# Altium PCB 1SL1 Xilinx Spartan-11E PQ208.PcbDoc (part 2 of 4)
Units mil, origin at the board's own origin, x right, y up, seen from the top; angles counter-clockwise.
Board outline 7086.61 x 1988.19 mil, 2 copper layers (Top Layer, Bottom Layer), stack 29.698 mil thick; 115 components, 126 nets, 642 pads, 225 vias.
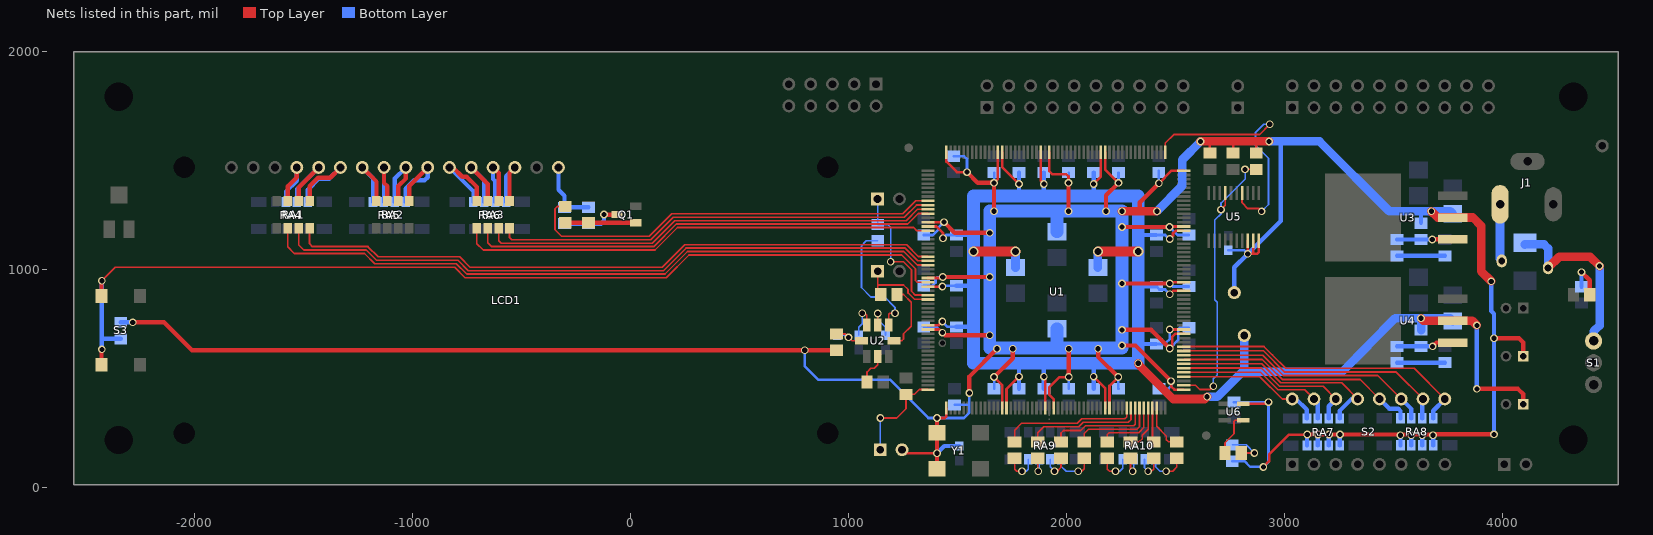
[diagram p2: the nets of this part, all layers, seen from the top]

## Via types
v1: diameter 35.43, hole 23.62, Top Layer to Bottom Layer, tented both sides, 168 vias
v2: diameter 59.06, hole 31.5, Top Layer to Bottom Layer, tented both sides, 27 vias
v3: diameter 47.24, hole 31.5, Top Layer to Bottom Layer, 18 vias
v4: diameter 47.24, hole 31.5, Top Layer to Bottom Layer, tented both sides, 11 vias
v5: diameter 35.43, hole 23.62, Top Layer to Bottom Layer, 1 vias

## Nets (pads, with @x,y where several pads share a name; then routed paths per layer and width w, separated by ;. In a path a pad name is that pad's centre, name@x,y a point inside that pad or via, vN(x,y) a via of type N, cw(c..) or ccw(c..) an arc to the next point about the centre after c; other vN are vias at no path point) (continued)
LCD_DB4: RA3.5 U1.15 | length 2201.6
  Top Layer w7.87: RA3.5@-704.87,1188.03 -704.87,1116.37 -676.13,1087.63 112.14,1087.63 215.49,1190.98 1298.78,1190.98 1313.55,1176.21 U1.15@1364.23,1176.21
LCD_DB5: RA3.6 U1.11 | length 2155.9
  Top Layer w7.87: RA3.6@-654.87,1188.03 -654.87,1121.49 -636.76,1103.38 105.62,1103.38 208.97,1206.72 1271.59,1206.72 1319.82,1254.95 U1.11@1364.23,1254.95
LCD_DB6: RA3.7 U1.10 | length 2095.7
  Top Layer w7.87: RA3.7@-604.87,1188.03 -604.87,1130.54 -593.45,1119.13 99.1,1119.13 202.44,1222.47 1263.83,1222.47 1316,1274.64 U1.10@1364.23,1274.64
LCD_DB7: RA3.8 U1.9 | length 2032.6
  Top Layer w7.87: RA3.8@-554.87,1188.03 -554.87,1144.52 -545.22,1134.87 92.57,1134.87 195.92,1238.22 1255.96,1238.22 1312.06,1294.32 U1.9@1364.23,1294.32
LCD_DB#0: LCD1.7 RA2.4 RA5.5 | length 360.5
  Top Layer w19.68: LCD1.7@-1230.65,1466.57 -1165.5,1401.41 RA2.4@-1165.5,1312.03
  Bottom Layer w19.68: LCD1.7@-1230.65,1466.57 -1181.24,1417.16 RA5.5@-1181.24,1308.09
LCD_DB#1: LCD1.8 RA2.3 RA5.6 | length 319.5
  Top Layer w19.68: LCD1.8@-1130.65,1466.57 -1130.65,1395.7 -1115.5,1380.54 RA2.3@-1115.5,1312.03
  Bottom Layer w19.68: RA5.6@-1131.24,1308.09 -1131.24,1465.98 LCD1.8@-1130.65,1466.57
LCD_DB#2: LCD1.9 RA2.2 RA5.7 | length 348.4
  Top Layer w19.68: RA2.2@-1065.5,1312.03 -1065.5,1380.94 -1030.65,1415.78 LCD1.9@-1030.65,1466.57
  Bottom Layer w19.68: RA5.7@-1081.24,1308.09 -1081.24,1415.98 LCD1.9@-1030.65,1466.57
LCD_DB#3: LCD1.10 RA2.1 RA5.8 | length 417.5
  Top Layer w19.68: RA2.1@-1015.5,1312.03 -1015.5,1381.72 LCD1.10@-930.65,1466.57
  Bottom Layer w19.68: RA5.8@-1031.24,1308.09 -1031.24,1368.34 -992.07,1407.51 -944.83,1407.51 -930.65,1421.68 LCD1.10@-930.65,1466.57
LCD_DB#4: LCD1.11 RA3.4 RA6.5 | length 431.4
  Top Layer w19.68: LCD1.11@-830.65,1466.57 -814.91,1466.57 -771.73,1423.39 -752.05,1423.39 -704.87,1376.21 RA3.4@-704.87,1312.03
  Bottom Layer w19.68: LCD1.11@-830.65,1466.57 -720.61,1356.53 RA6.5@-720.61,1308.09
LCD_DB#5: LCD1.12 RA3.3 RA6.6 | length 369.3
  Top Layer w19.68: LCD1.12@-730.65,1466.57 -654.87,1390.78 RA3.3@-654.87,1312.03
  Bottom Layer w19.68: LCD1.12@-730.65,1466.57 -670.61,1406.53 RA6.6@-670.61,1308.09
LCD_DB#6: LCD1.13 RA3.2 RA6.7 | length 327.8
  Top Layer w19.68: LCD1.13@-630.65,1466.57 -604.87,1440.78 RA3.2@-604.87,1312.03
  Bottom Layer w19.68: LCD1.13@-630.65,1466.57 -630.65,1413.61 -620.61,1403.57 RA6.7@-620.61,1308.09
LCD_DB#7: LCD1.14 RA3.1 RA6.8 | length 339.6
  Top Layer w19.68: RA3.1@-554.87,1312.03 -554.87,1442.35 LCD1.14@-530.65,1466.57
  Bottom Layer w19.68: RA6.8@-570.61,1308.09 -570.61,1426.61 LCD1.14@-530.65,1466.57
LCD_E: RA1.8 U1.21 | length 3018.1
  Top Layer w7.87: RA1.8@-1472.19,1188.03 -1472.19,1115.98 -1459.59,1103.38 -1204.67,1103.38 -1157.43,1056.13 -783.41,1056.13 -736.17,1008.89 144.76,1008.89 248.1,1112.24 1266.17,1112.24 1320.3,1058.1 U1.21@1364.23,1058.1
LCD_E#: LCD1.6 RA1.1 RA4.8 | length 493.5
  Top Layer w19.68: RA1.1@-1472.19,1312.03 -1472.19,1380.15 -1433.02,1419.32 -1377.9,1419.32 LCD1.6@-1330.65,1466.57
  Bottom Layer w19.68: RA4.8@-1480.06,1308.09 -1480.06,1364.4 -1429.28,1415.19 -1382.03,1415.19 LCD1.6@-1330.65,1466.57
LCD_LIGHT: R2.1 U1.8 | length 1938.7
  Top Layer w7.87: R2.1@-299.16,1287.43 -335.57,1287.43 -346.4,1276.61 -346.4,1180.15 -316.87,1150.62 86.05,1150.62 189.4,1253.97 1248.09,1253.97 1308.13,1314.01 U1.8@1364.23,1314.01
LCD_RS: RA1.6 U1.23 | length 3142.7
  Top Layer w7.87: RA1.6@-1572.19,1188.03 -1572.19,1101.79 -1542.28,1071.88 -1220.42,1071.88 -1173.17,1024.64 -799.16,1024.64 -751.91,977.39 157.8,977.39 261.15,1080.74 1253.01,1080.74 1315.02,1018.73 U1.23@1364.23,1018.73
LCD_RS#: LCD1.4 RA1.3 RA4.6 | length 350.7
  Top Layer w19.68: RA1.3@-1572.19,1312.03 -1572.19,1379.56 -1530.65,1421.09 LCD1.4@-1530.65,1466.57
  Bottom Layer w19.68: RA4.6@-1580.06,1308.09 -1580.06,1356.13 -1530.65,1405.54 LCD1.4@-1530.65,1466.57
LCD_RW: RA1.7 U1.22 | length 3079.2
  Top Layer w7.87: RA1.7@-1522.19,1188.03 -1522.19,1110.86 -1498.96,1087.63 -1212.54,1087.63 -1165.3,1040.39 -791.28,1040.39 -744.04,993.14 151.28,993.14 254.63,1096.49 1259.65,1096.49 1317.72,1038.42 U1.22@1364.23,1038.42
LCD_RW#: LCD1.5 RA1.2 RA4.7 | length 392.1
  Top Layer w19.68: RA1.2@-1522.19,1312.03 -1522.19,1375.03 LCD1.5@-1430.65,1466.57
  Bottom Layer w19.68: RA4.7@-1530.06,1308.09 -1530.06,1367.16 LCD1.5@-1430.65,1466.57
LEDS0: LED0.1 U1.102 | length 216.3
  Top Layer w7.87: U1.102@2413.44,363.22 2413.44,278.57 2457.73,234.28 2457.73,217.55 2467.57,207.71 LED0.1@2505.96,207.71
LEDS1: LED1.1 U1.101 | length 158
  Top Layer w7.87: U1.101@2393.76,363.22 2393.76,359.28 2393.76,213.61 LED1.1@2399.66,207.71
LEDS2: LED2.1 U1.100 | length 212.6
  Top Layer w7.87: LED2.1@2293.36,207.71 2333.72,207.71 2346.51,220.5 2346.51,237.24 2374.07,264.8 U1.100@2374.07,363.22
LEDS3: LED3.1 U1.99 | length 303.8
  Top Layer w7.87: LED3.1@2187.06,207.71 2187.06,241.17 2195.92,250.03 2330.76,250.03 2354.39,273.65 U1.99@2354.39,363.22
LEDS4: LED4.1 U1.98 | length 391
  Top Layer w7.87: LED4.1@2080.76,207.71 2080.76,246.09 2100.45,265.78 2322.89,265.78 2334.7,277.59 U1.98@2334.7,363.22
LEDS5: LED5.1 U1.97 | length 472.4
  Top Layer w7.87: LED5.1@1974.46,207.71 1974.46,248.06 1986.28,259.87 2065.02,259.87 2086.67,281.53 2308.13,281.53 2315.02,288.42 U1.97@2315.02,363.22
LEDS6: LED6.1 U1.96 | length 547.5
  Top Layer w7.87: LED6.1@1868.16,207.71 1868.16,249.05 1895.72,276.61 2056.16,276.61 2076.83,297.28 2283.52,297.28 2295.33,309.09 U1.96@2295.33,363.22
LEDS7: LED7.1 U1.95 | length 633.5
  Top Layer w7.87: LED7.1@1761.87,207.71 1761.87,260.86 1793.36,292.35 2049.63,292.35 2070.3,313.02 2266.79,313.02 2275.65,321.88 U1.95@2275.65,363.22
M0: JP5.1 R7.2 U1.52 | length 456.8
  Top Layer w7.87: v1(1145.72,316.96) 1220.53,316.96 1263.39,359.82 1263.39,425.43 1302.43,425.43 1324.86,447.87 U1.52@1364.23,447.87
  Bottom Layer w7.87: JP5.1@1145.72,171.29 v1(1145.72,316.96)
NetC15_1: C15.1 R11.2 U2.8 | length 181.4
  Top Layer w7.87: R11.2@944.15,702.79 984.31,702.79 1015.8,671.29 U2.8@1059.13,671.28
  Bottom Layer w7.87: C15.1@948.87,696.88 979.58,696.88 v1(1000.06,687.04)
NetC16_1: C16.1 U2.6 | length 166.8
  Top Layer w7.87: U2.6@1133.81,744.62 1134.01,744.81 v1(1134.01,796.78)
  Bottom Layer w7.87: v1(1134.01,796.78) 1134.01,768.95 1169.35,733.61 C16.1@1169.35,696.88
NetC19_1: C19.1 U2.7 | length 175.6
  Top Layer w7.87: v1(1063.05,797.28) 1074.86,797.28 1083.91,788.22 U2.7@1083.93,744.11
  Bottom Layer w7.87: C19.1@1047.3,696.88 1047.3,733.95 1063.05,749.7 v1(1063.05,797.28)
NetD1_2: D1.2 F1.2 S1.3 | length 832.9
  Top Layer w39.37: F1.2@4208.72,1005.94 4259.9,1057.11 4401.63,1057.12 v1(4444.94,1013.81)
  Bottom Layer w39.37: D1.2@4102.42,1113.11 4190.02,1113.22 4208.72,1094.52 F1.2@4208.72,1005.94 ; S1.3@4417.38,670.5 4417.38,714.6 4444.94,741.37 v1(4444.94,1013.81)
NetLCD1_16: LCD1.16 R8.1 R9.1 | length 304.7
  Bottom Layer w19.68: LCD1.16@-330.65,1466.57 -330.65,1364.2 -303.09,1336.65 -303.09,1283.5 R9.1@-192.86,1283.5
NetLED0_2: LED0.2 RA10.5 | length 218.1
  Top Layer w7.87: v1(2456.75,72.87) 2486.28,72.87 2505.96,92.55 LED0.2@2505.96,132.9
  Bottom Layer w7.87: RA10.5@2407.73,127.99 2407.73,93.54 2428.4,72.87 ; 2428.4,72.87 v1(2456.75,72.87) 2428.4,72.87
NetLED1_2: LED1.2 RA10.6 | length 141.8
  Top Layer w7.87: v1(2374.07,72.87) 2389.82,72.87 2399.66,82.71 LED1.2@2399.66,132.9
  Bottom Layer w7.87: RA10.6@2357.73,127.99 2357.73,89.2 v1(2374.07,72.87)
NetLED2_2: LED2.2 RA10.7 | length 121.1
  Top Layer w7.87: LED2.2@2293.36,132.9 2293.36,82.71 v1(2303.2,72.87)
  Bottom Layer w7.87: v1(2303.2,72.87) 2307.73,77.39 RA10.7@2307.73,127.99
NetLED3_2: LED3.2 RA10.8 | length 172.1
  Top Layer w7.87: LED3.2@2187.06,132.9 2187.06,82.71 2196.91,72.87 v1(2224.46,72.87)
  Bottom Layer w7.87: v1(2224.46,72.87) 2244.15,72.87 2257.73,86.45 RA10.8@2257.73,127.99
NetLED4_2: LED4.2 RA9.5 | length 200.5
  Top Layer w7.87: v1(2053.4,72.87) 2068.95,72.87 2080.76,84.68 LED4.2@2080.76,132.9
  Bottom Layer w7.87: RA9.5@1974.66,127.99 1974.66,96.49 1998.28,72.87 v1(2053.4,72.87)
NetLED5_2: LED5.2 RA9.6 | length 142.7
  Top Layer w7.87: v1(1944.94,72.87) 1956.75,72.87 1974.46,90.58 LED5.2@1974.46,132.9
  Bottom Layer w7.87: RA9.6@1924.66,127.99 1924.66,93.14 v1(1944.94,72.87)
NetLED6_2: LED6.2 RA9.7 | length 117.9
  Top Layer w7.87: LED6.2@1868.16,132.9 1868.16,74.84 v1(1870.13,72.87)
  Bottom Layer w7.87: v1(1870.13,72.87) 1874.66,77.39 RA9.7@1874.66,127.99
NetLED7_2: LED7.2 RA9.8 | length 166.5
  Top Layer w7.87: LED7.2@1761.87,132.9 1761.87,82.71 1771.71,72.87 v1(1795.33,72.87)
  Bottom Layer w7.87: v1(1795.33,72.87) 1815.02,72.87 1824.66,82.51 RA9.8@1824.66,127.99
NetLED8_1: LED8.1 R20.1 | length 176.9
  Top Layer w7.87: LED8.1@2801.24,156.53 v1(2861.28,156.53)
  Bottom Layer w7.87: R20.1@2759.9,193.93 2823.87,193.93 v1(2861.28,156.53)
NetLED8_2: LED8.2 U6.4 | length 206.6
  Top Layer w7.87: LED8.2@2726.43,156.53 2726.43,203.77 2767.77,245.11 2767.77,301.21 2773.68,307.12 U6.4@2810.09,307.12
NetLED9_1: LED9.1 R15.1 | length 186.8
  Top Layer w19.68: v1(4362.26,986.25) 4399.66,948.85 LED9.1@4399.66,881.92
  Bottom Layer w19.68: R15.1@4362.26,919.32 v1(4362.26,986.25)
NetQ1_1: Q1.1 R2.2 R3.2 | length 322.8
  Top Layer w19.68: R2.2@-299.16,1212.63 Q1.1@23.68,1212.63
NetQ1_3: Q1.3 R8.2 R9.2 | length 273.4
  Top Layer w19.68: v1(-121.99,1250.03) Q1.3@-62.94,1250.03
  Bottom Layer w19.68: R8.2@-303.09,1208.69 -135.77,1208.69 -121.99,1222.47 v1(-121.99,1250.03)
NetR10_2: R10.2 U2.2 | length 145.3
  Top Layer w7.87: R10.2@1084.7,482.31 1084.7,527.59 1102.42,545.31 1117.38,545.31 1133.91,561.84 U2.2@1133.91,598.46
NetR12_1: R12.1 R13.2 U3.1 | length 255.1
  Top Layer w19.68: v1@3678.01,1136.65 U3.1@3771.71,1136.65
  Bottom Layer w19.68: R12.1@3515.8,1135.86 3626.04,1135.86 v1(3677.22,1135.86)
NetR12_2: R12.2 R14.2 | length 220.5
  Bottom Layer w19.68: R12.2@3515.8,1061.06 R14.2@3736.28,1061.06
NetR17_1: R17.1 R18.2 U4.1 | length 263.2
  Top Layer w19.68: v1(3679.19,645.7) 3696.91,663.42 U4.1@3771.71,663.42
  Bottom Layer w19.68: R17.1@3515.8,645.7 v1(3679.19,645.7)
NetR17_2: R17.2 R19.1 | length 220.5
  Bottom Layer w19.68: R17.2@3515.8,570.9 R19.1@3736.28,570.9
PROG_B: R6.2 U1.106 U5.7 | length 1349.6
  Top Layer w7.87: U1.106@2537.46,467.55 2591.59,467.55 2611.28,447.87 2658.52,447.87 v1(2673.28,462.63) ; v1(2708.72,1272.67) 2728.4,1292.35 U5.7@2728.4,1348.46 ; v1(2818.96,1457.69) R6.2@2870.13,1457.71
  Bottom Layer w7.87: v1(2673.28,462.63) 2673.28,496.46 2691,514.18 2691,848.35 2680.17,859.18 2680.17,1225.11 2708.72,1253.65 2708.72,1303.18 2818.96,1413.43 v1(2818.96,1457.69)
PWR_IN: F1.1 J1.1 | length 311.8
  Bottom Layer w39.37: J1.1@3988.24,1346.49 3988.24,1047.28 F1.1@3996.12,1037.43
SW0: RA7.1 S2.16 U1.108 | length 702.2
  Top Layer w7.87: U1.108@2537.46,506.92 2886.87,506.92 2989.43,404.36 S2.16@3035.49,404.36
  Bottom Layer w19.68: S2.16@3035.49,404.36 3052.42,404.36 3102.22,354.56 3102.22,315.17 3102.42,314.98 3102.42,349.63
SW1: RA7.2 S2.15 U1.109 | length 812.8
  Top Layer w7.87: U1.109@2537.46,526.61 2889.82,526.61 2969.54,446.88 3092.97,446.88 S2.15@3135.49,404.36
  Bottom Layer w19.68: S2.15@3135.49,404.36 3152.42,387.43 RA7.2@3152.42,314.98 ; RA7.2@3152.22,319.91 S2.15@3152.22,387.63
SW2: RA7.3 S2.14 U1.110 | length 859.9
  Top Layer w7.87: U1.110@2537.46,546.29 2892.77,546.29 2976.43,462.63 3177.22,462.63 S2.14@3235.49,404.36
  Bottom Layer w19.68: RA7.3@3202.42,314.98 3202.42,371.29 S2.14@3235.49,404.36
SW3: RA7.4 S2.13 U1.111 | length 1005.5
  Top Layer w7.87: U1.111@2537.46,565.98 2895.36,565.98 2982.96,478.38 3261.47,478.38 S2.13@3335.49,404.36
  Bottom Layer w19.68: RA7.4@3252.42,314.98 3252.42,349.83 3306.94,404.36 S2.13@3335.49,404.36
SW4: RA8.1 S2.12 U1.112 | length 1127.4
  Top Layer w7.87: U1.112@2537.46,585.66 2897.94,585.66 2934.97,548.64 2989.48,494.13 3345.72,494.13 3435.49,404.36 S2.12@3434.31,404.36
  Bottom Layer w19.68: S2.12@3435.49,404.36 3480.73,359.12 3521.55,359.12 3531.55,349.12 RA8.1@3531.55,314.98
SW5: RA8.2 S2.11 U1.113 | length 1189.7
  Top Layer w7.87: U1.113@2537.46,605.35 2900.53,605.35 2937.3,568.57 2994.03,511.84 3428.01,511.84 S2.11@3535.49,404.36
  Bottom Layer w19.68: S2.11@3535.49,404.36 3581.55,358.3 RA8.2@3581.55,314.98
SW6: RA8.3 S2.10 U1.114 | length 1280.5
  Top Layer w7.87: U1.114@2537.46,625.03 2903.12,625.03 3000.56,527.59 3512.26,527.59 S2.10@3635.49,404.36
  Bottom Layer w19.68: RA8.3@3631.55,314.98 3631.55,400.43 S2.10@3635.49,404.36
SW7: RA8.4 S2.9 U1.115 | length 1409.3
  Top Layer w7.87: U1.115@2537.46,644.72 2905.7,644.72 2944.74,605.67 3005.11,545.31 3594.54,545.31 S2.9@3735.49,404.36
  Bottom Layer w19.68: RA8.4@3681.55,314.98 3681.55,350.43 S2.9@3735.49,404.36
TDI_C: U1.157 U5.4 | length 1188.3
  Top Layer w7.87: U1.157@2452.81,1536.45 2452.81,1578.77 2491.2,1617.16 2884.9,1617.16 v1(2932.14,1664.4) ; U5.4@2805.17,1348.46 2805.17,1304.17 2831.75,1277.59 2882.22,1277.59 v1(2894.94,1264.87)
  Bottom Layer w7.87: v1(2894.94,1264.87) 2926.24,1296.17 2926.24,1508.5 2866.2,1568.54 2866.2,1626.02 2904.58,1664.4 v1(2932.14,1664.4)
TEST: R16.2 S3.1 S3.2 U1.27 | length 4504
  Top Layer w7.87: v1(-2425.14,946.88) -2363.53,1008.5 -807.03,1008.5 -759.2,960.66 163.44,960.66 267.77,1064.99 1244.15,1064.99 1307.14,1002 1307.14,947.87 1315.02,939.99 U1.27@1364.23,939.99
  Top Layer w19.68: S3.1@-2427.11,560.66 -2427.11,629.95 v1(-2425.14,631.92) ; S3.2@-2427.11,876.02 v1@-2427.11,944.91
  Bottom Layer w19.68: v1(-2425.14,631.92) v1(-2425.14,946.88) ; -2425.14,681.13 R16.2@-2338.53,681.13
VCCINT: C3.1 C7.1 C8.1 C10.1 C20.1 C21.1 C25.1 C26.1 C28.1 C29.1 C30.1 C32.1 C34.2 C38.1 C39.1 C41.1 R18.1 TP3.1 U1.14 U1.28 U1.37 U1.67 U1.76 U1.90 U1.119 U1.128 U1.142 U1.172 U1.186 U1.195 U4.2 | length 9314.6
  Top Layer w11.81: U1.37@1364.14,742.67 1412.97,742.67 v1(1430.17,759.87) ; U1.28@1364.14,919.83 v1@1430.17,919.83 ; U1.14@1364.14,1195.43 1403.09,1195.43 1433.13,1165.39 v1(1433.13,1141.76) ; U1.195@1704.69,1535.98 1704.69,1467.64 v1(1781.55,1390.78) ; U1.67@1724.38,362.75 1724.38,449.75 v1(1781.55,506.92) ; U1.186@1881.86,1535.98 1881.86,1404.65 v1(1895.72,1390.78) ; v1(1895.72,506.92) 1901.54,501.1 U1.76@1901.54,362.75 ; v1(2124.07,506.92) 2177.13,453.86 U1.90@2177.13,362.75 ; v1(2124.07,1390.78) 2157.45,1424.16 U1.172@2157.45,1535.98 ; v1@2473.48,722.98 U1.119@2537.37,722.98 ; v1(2473.48,884.87) 2488.76,900.15 U1.128@2537.37,900.15 ; v1(2473.48,1137.83) 2488.24,1152.59 2488.24,1164.13 2499.86,1175.74 U1.142@2537.37,1175.74
  Top Layer w19.68: v1(3881.94,450.82) 4070.92,450.82 4094.54,427.2 C3.1@4094.54,379.95
  Top Layer w39.37: v1(2328.8,567.94) 2332.73,560.07 2488.47,404.34 2634.67,404.34 v1(2644.74,414.4) ; v1(3626.04,774.64) 3637.26,763.42 3860.69,763.42 v1(3881.94,742.16)
  Top Layer w47.24: v4(1572.89,1080.74) v4(1765.8,1080.74) ; v4(2143.76,1080.74) v4(2328.8,1080.74)
  Bottom Layer w11.81: v1(1430.17,759.87) 1454.78,735.27 C32.1@1494.15,735.27 ; v1(1430.17,920.31) 1430.17,924.24 C25.1@1494.15,924.24 ; v1(1433.13,1141.76) 1447.89,1156.53 C20.1@1494.15,1156.53 ; C34.2@2411.47,656.53 2449.72,656.53 ; C26.1@2411.47,920.31 2425.25,906.53 2451.83,906.53 v1(2473.48,884.87) ; C21.1@2411.47,1156.53 2451.83,1156.53 2470.53,1137.83 v1(2473.48,1137.83) ; 2449.29,656.95 2453.2,660.86 ; 2453.69,660.36 2473.48,680.15 v1(2473.48,723.46)
  Bottom Layer w19.68: C32.1@1494.15,735.27 1572.89,735.27 ; C25.1@1494.15,924.24 1572.89,924.24 ; C20.1@1494.15,1156.53 1572.89,1156.53 ; C38.1@1781.55,451.8 v1(1781.55,506.92) 1781.55,560.07 ; 1781.55,1340.58 v1(1781.55,1390.78) C7.1@1781.55,1442.94 ; C39.1@1895.72,451.8 1895.72,560.07 ; 1895.72,1340.58 C8.1@1895.72,1442.94 ; C41.1@2124.07,451.8 2124.07,560.07 ; 2124.07,1340.58 C10.1@2124.07,1442.94 ; 2328.8,656.53 C34.2@2411.47,656.53 ; 2328.8,920.31 C26.1@2411.47,920.31 ; 2328.8,1156.53 C21.1@2411.47,1156.53 ; v1(3881.94,450.82) v1(3881.94,742.16)
  Bottom Layer w39.37: C28.1@1765.8,1006.92 v4(1765.8,1080.74) ; C29.1@2143.76,1006.92 v4(2143.76,1080.74) ; v1(2644.74,414.4) 2691.98,414.4 2806.16,528.57 3263.83,528.57 3506.94,774.64 3758.91,774.64 C30.1@3771.71,761.84 ; 2815.02,528.57 TP3.1@2815.02,694.91 ; R18.1@3626.04,720.5 v1(3626.04,774.64)
  Bottom Layer w59.06: 1572.89,567.94 v1(2328.8,567.94) 2328.8,1335.66 2124.07,1335.66 1572.89,1335.66 v4(1572.89,1080.74) 1572.89,567.94
VCCO: C2.1 C4.1 C5.2 C6.1 C9.1 C11.1 C12.1 C14.1 C17.2 C18.2 C22.2 C23.1 C24.2 C31.1 C33.1 C35.1 C36.2 C37.1 C40.1 C42.1 C43.1 C44.2 C45.1 JP5.2 R4.1 R5.1 R6.1 R11.1 R13.1 R16.1 R20.2 RA7.5 RA7.6 RA7.7 RA7.8 RA8.5 RA8.6 RA8.7 RA8.8 TP2.1 U1.13 U1.26 U1.38 U1.53 U1.66 U1.78 U1.91 U1.105 U1.118 U1.130 U1.143 U1.156 U1.171 U1.184 U1.196 U1.208 U3.2 U5.18 U5.19 U5.20 U6.5 Y1.1 Y1.4 | length 21130.7
  Top Layer w11.81: JP5.2@1245.72,171.29 1261.47,155.54 v1(1405.57,155.54) ; U1.38@1364.14,722.98 1415.88,722.98 v1@1441.98,696.88 ; U1.26@1364.14,959.2 1427.73,959.2 v1(1432.14,963.61) v1@1437.06,963.61 ; U1.13@1364.14,1215.11 v1@1438.05,1215.11 ; v1(1405.57,316.96) 1441,316.96 1448.79,324.75 U1.53@1448.79,362.75 ; U1.208@1448.79,1535.98 1448.79,1493.23 1497.1,1444.91 v1(1543.36,1444.91) ; v1(1667.38,504.95) 1704.69,467.64 U1.66@1704.69,362.75 ; v1(1667.38,1395.7) 1685.01,1413.33 U1.196@1685.01,1535.98 ; U1.184@1921.23,1535.98 1921.23,1448.94 1934.11,1436.05 1998.09,1436.05 2008.91,1425.23 v1(2008.91,1395.7) ; U1.78@1940.91,362.75 1940.91,403.66 1921.31,423.26 1921.31,458.69 1967.57,504.95 v1(2009.9,504.95) ; U1.171@2177.13,1535.98 2177.13,1456.81 v1(2238.24,1395.7) ; U1.91@2196.82,362.75 2196.82,464.51 v1(2237.26,504.95) ; v1(2423.28,1393.73) 2481.35,1451.8 U1.156@2537.46,1451.8 ; v1(2472.5,1192.94) 2472.5,1195.43 U1.143@2537.37,1195.43 ; v1(2473.48,635.86) 2484.97,647.35 2484.97,689.9 2498.37,703.3 U1.118@2537.37,703.3 ; v1(2473.48,934.09) v1@2479.39,939.99 ; v1(2479.39,486.25) 2479.39,462.63 2494.62,447.39 U1.105@2537.37,447.39 ; v1@2479.86,939.52 U1.130@2537.37,939.52 ; R4.1@2657.54,1532.51 2657.54,1578.77 ; R5.1@2763.83,1532.51 2763.83,1578.77 ; U6.5@2810.09,381.92 2918.36,381.92 v1(2926.24,389.8) ; U5.18@2830.76,1129.95 v1(2830.76,1069.91) 2874.07,1069.91 2881.94,1077.79 U5.20@2881.94,1129.95 ; 2856.35,1069.91 U5.19@2856.35,1129.95 ; R6.1@2870.13,1532.51 2870.13,1587.63 2871.12,1588.61 ; v1(2902.61,92.55) 2929.11,119.04 2929.11,149.94 3020.33,241.17 v1(3103.8,241.17)
  Top Layer w19.68: v1(-2283.41,755.94) -2139.71,755.94 -2011.76,627.98 v1(799.25,627.98) R11.1@944.15,627.98 ; Y1.1@1405.57,72.87 v1(1405.57,316.96) ; v1(1432.14,963.61) v1(1647.69,963.61) ; v1(1438.05,1215.58) 1487.26,1166.37 v1(1647.69,1166.37) ; v1@1441.98,696.88 v1(1647.69,696.88) ; v1(1543.36,1444.91) 1592.57,1395.7 v1(1667.38,1395.7) v1(1667.38,1265.78) ; v1(1554.19,432.12) 1554.19,507.91 v1(1681.16,634.87) ; v1(1667.38,504.95) 1753.01,590.58 v1(1753.01,634.87) ; v1(2008.91,1265.78) v1(2008.91,1395.7) ; v1(2009.9,504.95) v1(2009.9,634.87) ; v1(2144.74,634.87) 2144.74,597.47 v1(2237.26,504.95) ; v1(2181.16,1265.78) 2181.16,1338.61 v1(2238.24,1395.7) ; v1(2253.99,649.64) 2316,649.64 v1(2479.39,486.25) ; v1(2253.99,721.49) 2387.85,721.49 v1(2473.48,635.86) ; v1(2253.99,934.09) v1(2473.48,934.09) ; v1(2253.99,1192.94) v1(2472.5,1192.94) ; 2335.68,1265.78 2335.68,1306.13 v1(2423.28,1393.73) ; v1(2614.23,1585.66) 2624.07,1578.77 2860.29,1578.77 ; v1(3103.8,241.17) v1@3682.93,241.17 ; v1(3681.16,238.22) 3685.09,242.16 v1(3960.68,242.16) ; v1(3960.68,683.1) 4074.86,683.1 4094.54,663.42 C2.1@4094.54,600.43
  Top Layer w39.37: v1(2253.99,1265.78) v1(2414.43,1265.78) ; v1(2614.23,1585.66) v1(2929.19,1585.66) ; v1(3673.28,1265.78) 3702.42,1236.65 3863.83,1236.65 3901.63,1198.85 3901.63,990.19 v1(3947.89,943.93)
  Bottom Layer w11.81: v1(799.25,627.98) 799.25,554.17 860.29,493.14 1191,493.14 1366.2,316.96 1529.58,316.96 1554.19,341.57 v1(1554.19,432.12) ; C31.1@1344.54,735.27 1403.6,735.27 v1(1430.17,708.69) ; C22.2@1344.54,924.24 1384.9,924.24 1398.68,938.02 1398.68,953.77 1408.52,963.61 v1(1432.14,963.61) ; C17.2@1344.54,1156.53 1386.87,1156.53 1410.49,1180.15 1410.49,1188.02 v1(1438.05,1215.58) ; C5.2@1482.34,1517.75 1530.57,1517.75 1543.36,1504.95 v1(1543.36,1444.91) ; C36.2@1486.28,377 1554.19,377 ; C37.1@1667.38,451.8 v1(1667.38,504.95) ; v1(1667.38,1395.7) C6.1@1667.38,1442.94 ; v1(2008.91,1395.7) C9.1@2009.9,1442.94 ; C40.1@2009.9,451.8 v1(2009.9,504.95) ; v1(2237.26,504.95) 2237.26,452.79 C42.1@2238.24,451.8 ; v1(2238.24,1395.7) C11.1@2238.24,1442.94 ; C43.1@2423.28,451.8 2467.57,451.8 2479.39,463.61 v1(2479.39,486.25) ; v1(2423.28,1393.73) C12.1@2423.28,1451.8 ; v1(2472.5,1192.94) 2508.91,1156.53 C18.2@2561.08,1156.53 ; v1(2473.48,635.86) 2511.87,674.24 2511.87,723.46 2519.74,731.33 C35.1@2561.08,731.33 ; v1(2473.48,934.09) 2487.26,920.31 C24.2@2561.08,920.31 ; C4.1@2741.2,1086.65 2814.03,1086.65 v1(2830.76,1069.91) ; R20.2@2759.9,119.13 2816,119.13 2842.56,92.55 v1(2902.61,92.55) 2926.24,116.17 v1(2926.24,389.8) C44.2@2767.77,389.8
  Bottom Layer w19.68: R16.1@-2338.53,755.94 v1(-2283.41,755.94) ; v1(1405.57,155.54) 1439.03,189.01 C45.1@1507.93,189.01 ; TP2.1@2769.07,891.75 2769.07,1008.22 v1(2830.76,1069.91) 2982.34,1220.5 2982.34,1585.66 v1(2929.19,1585.66) ; RA7.8@3102.42,190.98 v1@3102.42,239.79 ; RA7.7@3152.42,190.98 v1@3152.42,239.79 ; RA7.6@3202.42,190.98 v1@3202.42,239.79 ; RA7.5@3252.42,190.98 v1@3252.42,239.79 ; RA8.8@3531.55,190.98 v1@3531.55,239.79 ; RA8.7@3581.55,190.98 v1@3581.55,239.79 ; R13.1@3626.04,1212.63 3626.04,1266.76 ; RA8.6@3631.55,190.98 v1@3631.55,239.79 ; RA8.5@3681.55,190.98 v1@3681.55,239.79 ; v1(3947.89,943.93) 3947.89,808.1 3960.68,795.31 v1(3960.68,683.1) v1(3960.68,242.16)
  Bottom Layer w39.37: v1(2414.43,1265.78) 2530.57,1381.92 2530.57,1502 v1(2614.23,1585.66) ; v1(2929.19,1585.66) 3160.49,1585.66 3480.37,1265.78 3759.9,1265.78 C14.1@3771.71,1253.97
  Bottom Layer w59.06: 1956.75,639.8 C33.1@1956.75,726.41 ; C23.1@1956.75,1171.29 1956.75,1265.78 ; 1956.75,1265.78 v1(2253.99,1265.78) 2253.99,638.81 1647.69,638.81 v1(1647.69,696.88) v1(1647.69,963.61) 1647.69,1265.78 v1(1667.38,1265.78) 1956.75,1265.78
  other v1: 3531.16,238.22 3581.16,238.22 3631.16,238.22 3153.8,241.17 3203.8,241.17 3253.8,241.17
Xout: R22.2 U2.5 | length 590.7
  Top Layer w7.87: U2.5@1183.93,744.11 1183.91,780.35 1183.91,792.16 1189.03,797.28 v1(1212.65,797.28)
  Bottom Layer w7.87: R22.2@1134.36,1130.16 1080.95,1130.16 1059.11,1104.38 1059.11,915.39 1102.42,872.08 1165.97,872.08 1212.65,825.39 v1(1212.65,797.28) v1@1200.84,809.09
Xout_Alt: JP3.1 R22.1 U1.30 | length 630.6
  Top Layer w7.87: v1(1192.97,1033.5) 1252.02,1033.5 1288.75,996.77 1288.75,898.34 1306.16,880.94 U1.30@1364.23,880.94
  Bottom Layer w7.87: JP3.1@1133.65,1321.29 1133.65,1205.67 1134.36,1204.96 1178.98,1204.96 1192.97,1190.98 v1(1192.97,1033.5)
Yout: R21.2 U2.4 | length 309.9
  Top Layer w7.87: U2.4@1208.73,671.28 1244.15,671.29 1252.02,679.17 1252.02,702.79 1287.44,738.2 1287.44,847.91 1251.91,883.44 R21.2@1222.29,883.44
Yout_Alt: JP4.1 R21.1 U1.31 | length 376.1
  Top Layer w7.87: JP4.1@1133.65,990.58 1133.65,897.28 R21.1@1147.49,883.44 ; 1137.59,927.2 1252.02,927.2 1273.01,906.22 1273.01,890.47 1302.22,861.25 U1.31@1364.23,861.25
pads on no net: HDR2.1 HDR3.1 LCD1.M1 LCD1.M2 LCD1.M3 LCD1.M4 RA1.4 RA1.5 RA4.5 RA4.STP RA5.STP RA6.STP RA7.STP RA8.STP RA9.STP RA10.STP U1.3 U1.24 U1.29 U1.33 U1.34 U1.35 U1.36 U1.40 U1.41 U1.42 U1.43 U1.44 U1.45 U1.46 U1.47 U1.48 U1.49 U1.55 U1.56 U1.57 U1.58 U1.59 U1.60 U1.61 U1.62 U1.63 U1.64 U1.68 U1.69 U1.70 U1.71 U1.73 U1.74 U1.75 U1.81 U1.82 U1.83 U1.84 U1.86 U1.87 U1.88 U1.89 U1.93 U1.94 U1.116 U1.139 U1.140 U1.141 U1.145 U1.146 U1.147 U1.148 U1.149 U1.150 U1.151 U1.152 U1.154 U1.192 U1.193 U1.194 U1.198 U1.199 U1.200 U1.201 U1.202 U1.203 U1.204 U1.205 U1.206 U1.FID1 U1.FID2 U2.0 U2.1 U3.4 U4.4 U5.2 U5.9 U5.12 U5.13 U5.14 U5.15 U5.16 U6.1

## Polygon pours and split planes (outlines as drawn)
GND on Top Layer "Top Layer-GND" (solid, remove dead copper, pour order 8): -2555.06,9.87 -2555.06,1998.06 4531.55,1998.06 4531.55,9.87
GND on Bottom Layer "Bottom Layer-GND" (solid, remove dead copper, pour order 10): 4531.35,9.88 4531.35,1998.07 -2555.26,1998.07 -2555.26,9.88

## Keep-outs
Keep-Out Layer:
  circle w7.87: c4324.86,1791.37 r157.48
  circle w7.87: c-2348.37,1791.37 r157.48
  circle w7.87: c4324.86,217.55 r157.48
  circle w7.87: c-2348.37,216.57 r157.48
  lines w25: -2555.06,9.87 4531.55,9.87 4531.55,1998.06 -2555.06,1998.06 -2555.06,9.87

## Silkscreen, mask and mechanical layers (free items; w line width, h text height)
Top Overlay:
  drawing of 3334 lines, arcs and shapes, not listed
  text "SL" at -421.91,1833.53 h51.18
  text "REV 1.01" at -221.91,1833.53 h51.18
  text "CONTRAST" at -2480.26,1057.12 h39.37
  text "PWR" at 4504.94,819.87 h47.24 r90
  text "TEST/" at -2413.34,462.63 h39.37
  text "RESET" at -2421.2,395.69 h39.37
  text "7" at 1759.9,265.78 h47.24
  text "6" at 1854.39,265.78 h47.24
  text "5" at 1960.68,265.78 h47.24
  text "4" at 2063.05,265.78 h47.24
  text "3" at 2173.28,265.78 h47.24
  text "2" at 2275.65,265.78 h47.24
  text "1" at 2385.88,265.78 h47.24
  text "0" at 2488.24,265.78 h47.24
  text "DONE" at 2679.9,47.11 h47.24
1_BOARD_OUTLINE:
  the board outline again, w7.87
2_DIMENSION:
  text "Dimensions in millimetres (mm)" at -2555.06,-305.09 h29.53
15_TOP_COURTYARD:
  lines w7.87: -2543.25,1612.24 4531.55,1612.24
Drill Drawing:
  circle w5: c2664.56,5582.5 r25
  circle w5: c2664.56,5020 r15
  circle w5: c2664.56,5020 r25
  lines w5: 2595.5,4511.25 5464.73,4511.25 ; 2595.5,5636.25 5464.73,5636.25 ; 3000.66,4398.75 3000.66,5748.75 ; 3516.02,4398.75 3516.02,5748.75 ; 4517.22,4398.75 4517.22,5748.75 ; 4888.63,4398.75 4888.63,5748.75 ; 2595.5,4398.75 5464.73,4398.75 5464.73,5748.75 2595.5,5748.75 2595.5,4398.75 ; 2639.56,4545 2689.56,4545 2689.56,4595 2639.56,4595 2639.56,4545 ; 2639.56,4707.5 2689.56,4707.5 2664.56,4657.5 2639.56,4707.5 ; 2639.56,4782.5 2652.06,4782.5 2652.06,4770 2677.06,4770 2677.06,4782.5 2689.56,4782.5 2689.56,4807.5 2677.06,4807.5 2677.06,4820 2652.06,4820 2652.06,4807.5 2639.56,4807.5 2639.56,4782.5 ; 2639.56,4882.5 2664.56,4895 2689.56,4882.5 2677.06,4907.5 2689.56,4932.5 2664.56,4920 2639.56,4932.5 2652.06,4907.5 2639.56,4882.5 ; 2639.56,5120 2652.06,5120 2664.56,5107.5 2677.06,5120 2689.56,5120 2677.06,5132.5 2689.56,5145 2677.06,5145 2664.56,5157.5 2652.06,5145 2639.56,5145 2652.06,5132.5 2639.56,5120 ; 2639.56,5220 2689.56,5220 2689.56,5270 2639.56,5270 2639.56,5220 ; 2639.56,5357.5 2664.56,5332.5 2689.56,5357.5 2664.56,5382.5 2639.56,5357.5 ; 2639.56,5445 2639.56,5457.5 2652.06,5470 2639.56,5482.5 2639.56,5495 2652.06,5495 2664.56,5482.5 2677.06,5495 2689.56,5495 2689.56,5482.5 2677.06,5470 2689.56,5457.5 2689.56,5445 2677.06,5445 2664.56,5457.5 2652.06,5445 2639.56,5445 ; 2649.56,4555 2679.56,4555 2679.56,4585 2649.56,4585 2649.56,4555
  text "Symbol" at 2663,5670 h54
  text "Hit Count" at 3034.41,5670 h54
  text "Finished Hole Size" at 3549.77,5670 h54
  text "Plated" at 4550.97,5670 h54
  text "Hole Type" at 4922.38,5670 h54
  text "1" at 3034.41,5557.5 h45
  text "20,00mil (0,508mm)" at 3549.77,5557.5 h45
  text "NPTH" at 4550.97,5557.5 h45
  text "Round" at 4922.38,5557.5 h45
  text "1" at 3034.41,5445 h45
  text "39,37mil (1,000mm)" at 3549.77,5445 h45
  text "PTH" at 4550.97,5445 h45
  text "Slot" at 4922.38,5445 h45
  text "2" at 3034.41,5332.5 h45
  text "39,37mil (1,000mm)" at 3549.77,5332.5 h45
  text "PTH" at 4550.97,5332.5 h45
  text "Slot" at 4922.38,5332.5 h45
  text "3" at 3034.41,5220 h45
  text "43,31mil (1,100mm)" at 3549.77,5220 h45
  text "PTH" at 4550.97,5220 h45
  text "Round" at 4922.38,5220 h45
  text "4" at 3034.41,5107.5 h45
  text "98,43mil (2,500mm)" at 3549.77,5107.5 h45
  text "NPTH" at 4550.97,5107.5 h45
  text "Round" at 4922.38,5107.5 h45
  text "4" at 3034.41,4995 h45
  text "129,92mil (3,300mm)" at 3549.77,4995 h45
  text "NPTH" at 4550.97,4995 h45
  text "Round" at 4922.38,4995 h45
  text "6" at 3034.41,4882.5 h45
  text "29,53mil (0,750mm)" at 3549.77,4882.5 h45
  text "PTH" at 4550.97,4882.5 h45
  text "Round" at 4922.38,4882.5 h45
  text "58" at 3034.41,4770 h45
  text "31,50mil (0,800mm)" at 3549.77,4770 h45
  text "PTH" at 4550.97,4770 h45
  text "Round" at 4922.38,4770 h45
  text "95" at 3034.41,4657.5 h45
  text "35,43mil (0,900mm)" at 3549.77,4657.5 h45
  text "PTH" at 4550.97,4657.5 h45
  text "Round" at 4922.38,4657.5 h45
  text "170" at 3034.41,4545 h45
  text "23,62mil (0,600mm)" at 3549.77,4545 h45
  text "PTH" at 4550.97,4545 h45
  text "Round" at 4922.38,4545 h45
  text "344 Total" at 3034.41,4432.5 h45
  text "Slot definitions :" at 2663,4328.77 h45
  text "Routed Path Length" at 3430.52,4328.77 h45
  text "= Calculated from tool start centre position to tool end centre position." at 4250.52,4328.77 h45
  text "Hole Length" at 3430.52,4258.79 h45
  text "= Routed Path Length + Tool Size = Slot length as defined in the PCB layout" at 3943.12,4258.79 h45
